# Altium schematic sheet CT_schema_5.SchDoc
size 367 x 243 mm
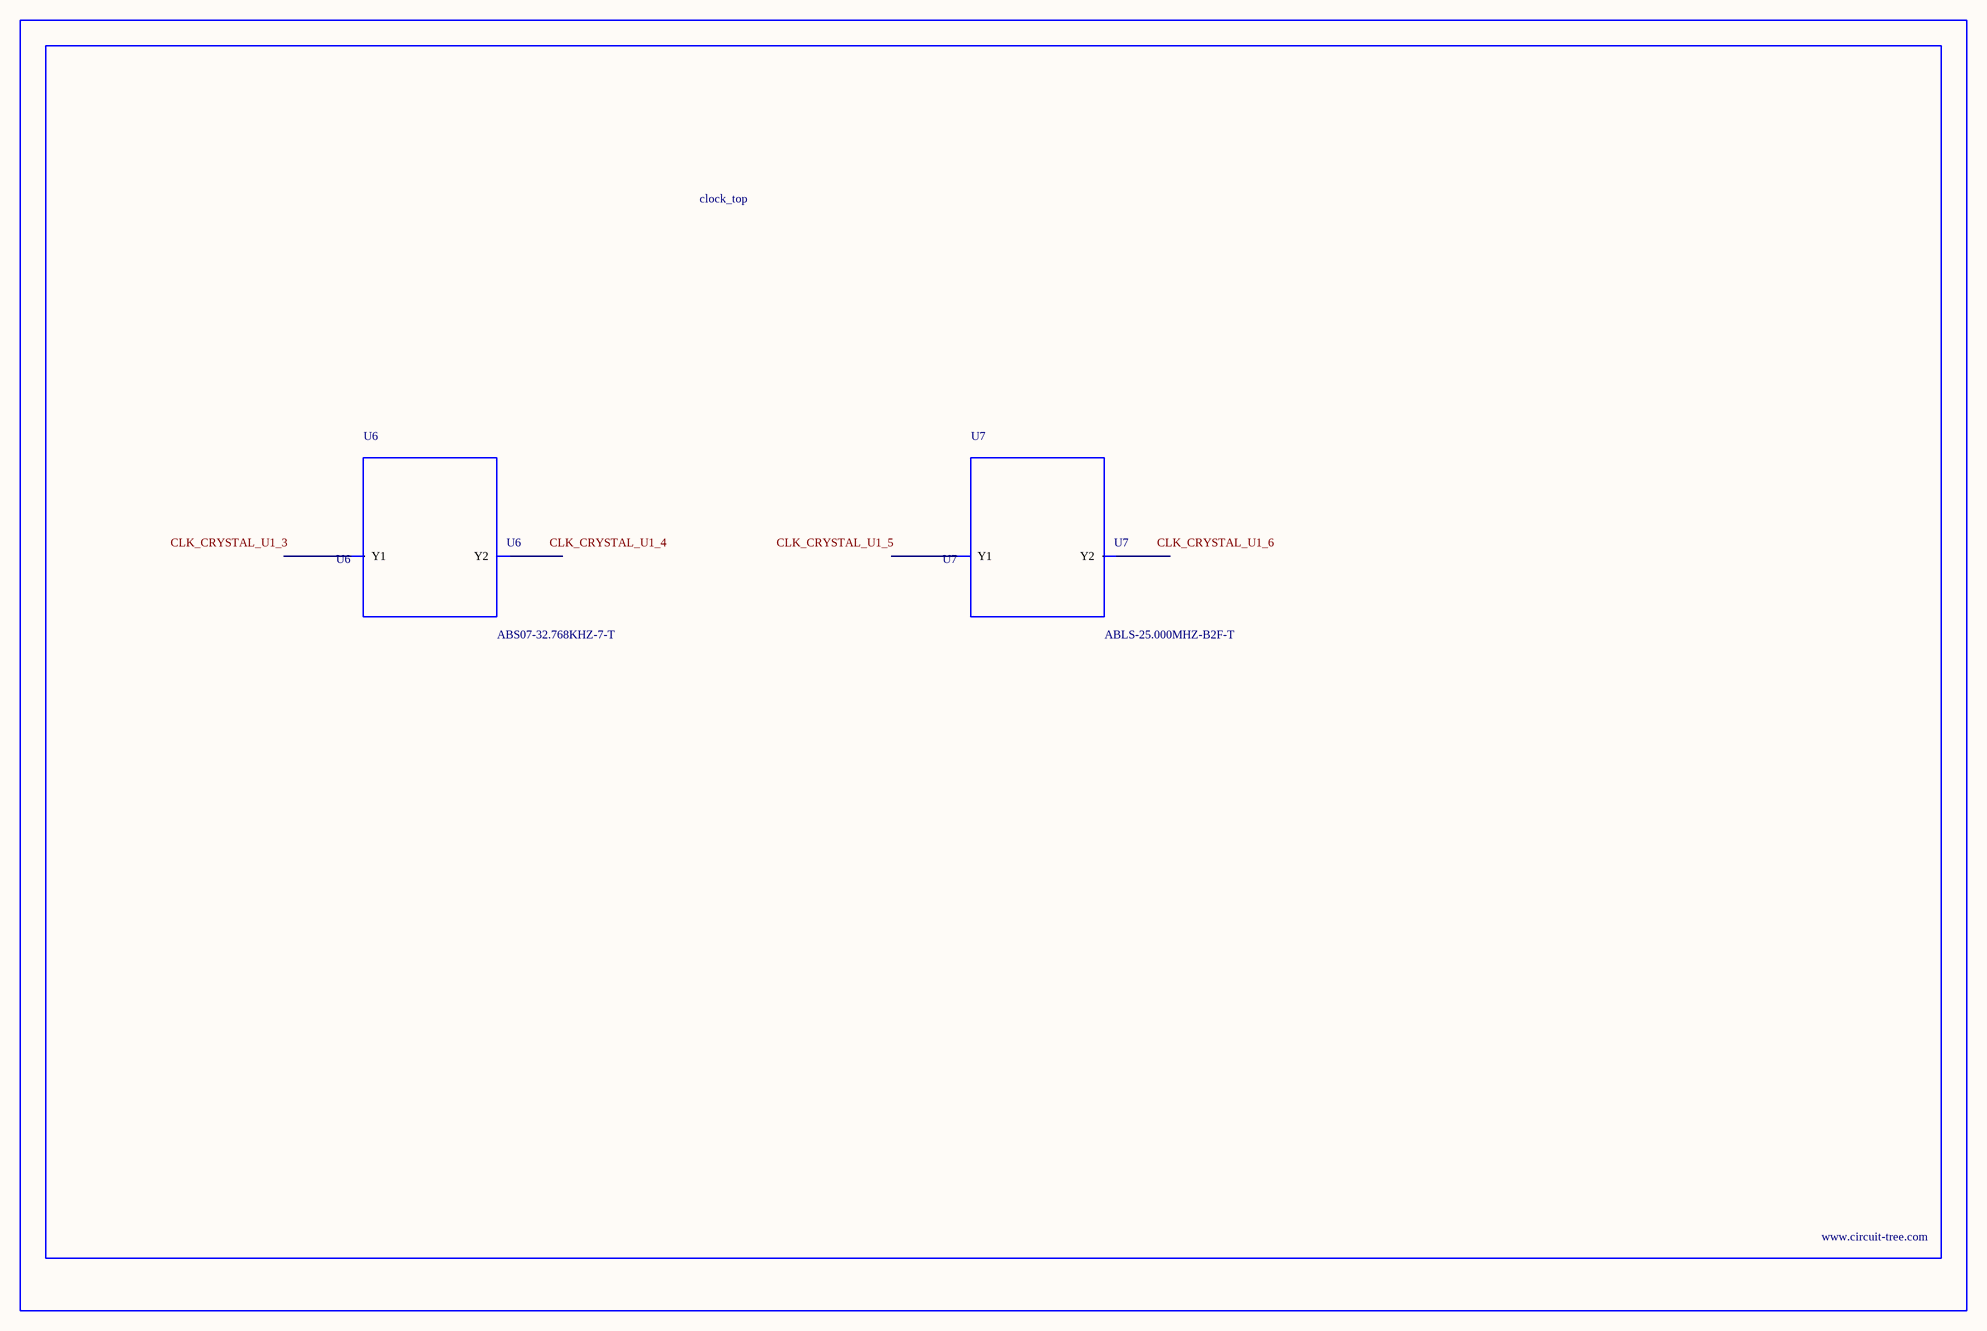
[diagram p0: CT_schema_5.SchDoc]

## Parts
BORDER4  (no value)
U6  ABS07-32.768KHZ-7-T  [ABS07-32.768KHZ-7-T]
U7  ABLS-25.000MHZ-B2F-T  [ABLS-25.000MHZ-B2F-T]

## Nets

Not connected (* = marked no-connect by the designer): U6 1(Y1) 2(Y2); U7 1(Y1) 2(Y2)

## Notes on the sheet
- Labels drawn without touching a wire or pin: CLK_CRYSTAL_U1_3, CLK_CRYSTAL_U1_4, CLK_CRYSTAL_U1_5, CLK_CRYSTAL_U1_6

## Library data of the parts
BORDER4 = BORDER_PAGE4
